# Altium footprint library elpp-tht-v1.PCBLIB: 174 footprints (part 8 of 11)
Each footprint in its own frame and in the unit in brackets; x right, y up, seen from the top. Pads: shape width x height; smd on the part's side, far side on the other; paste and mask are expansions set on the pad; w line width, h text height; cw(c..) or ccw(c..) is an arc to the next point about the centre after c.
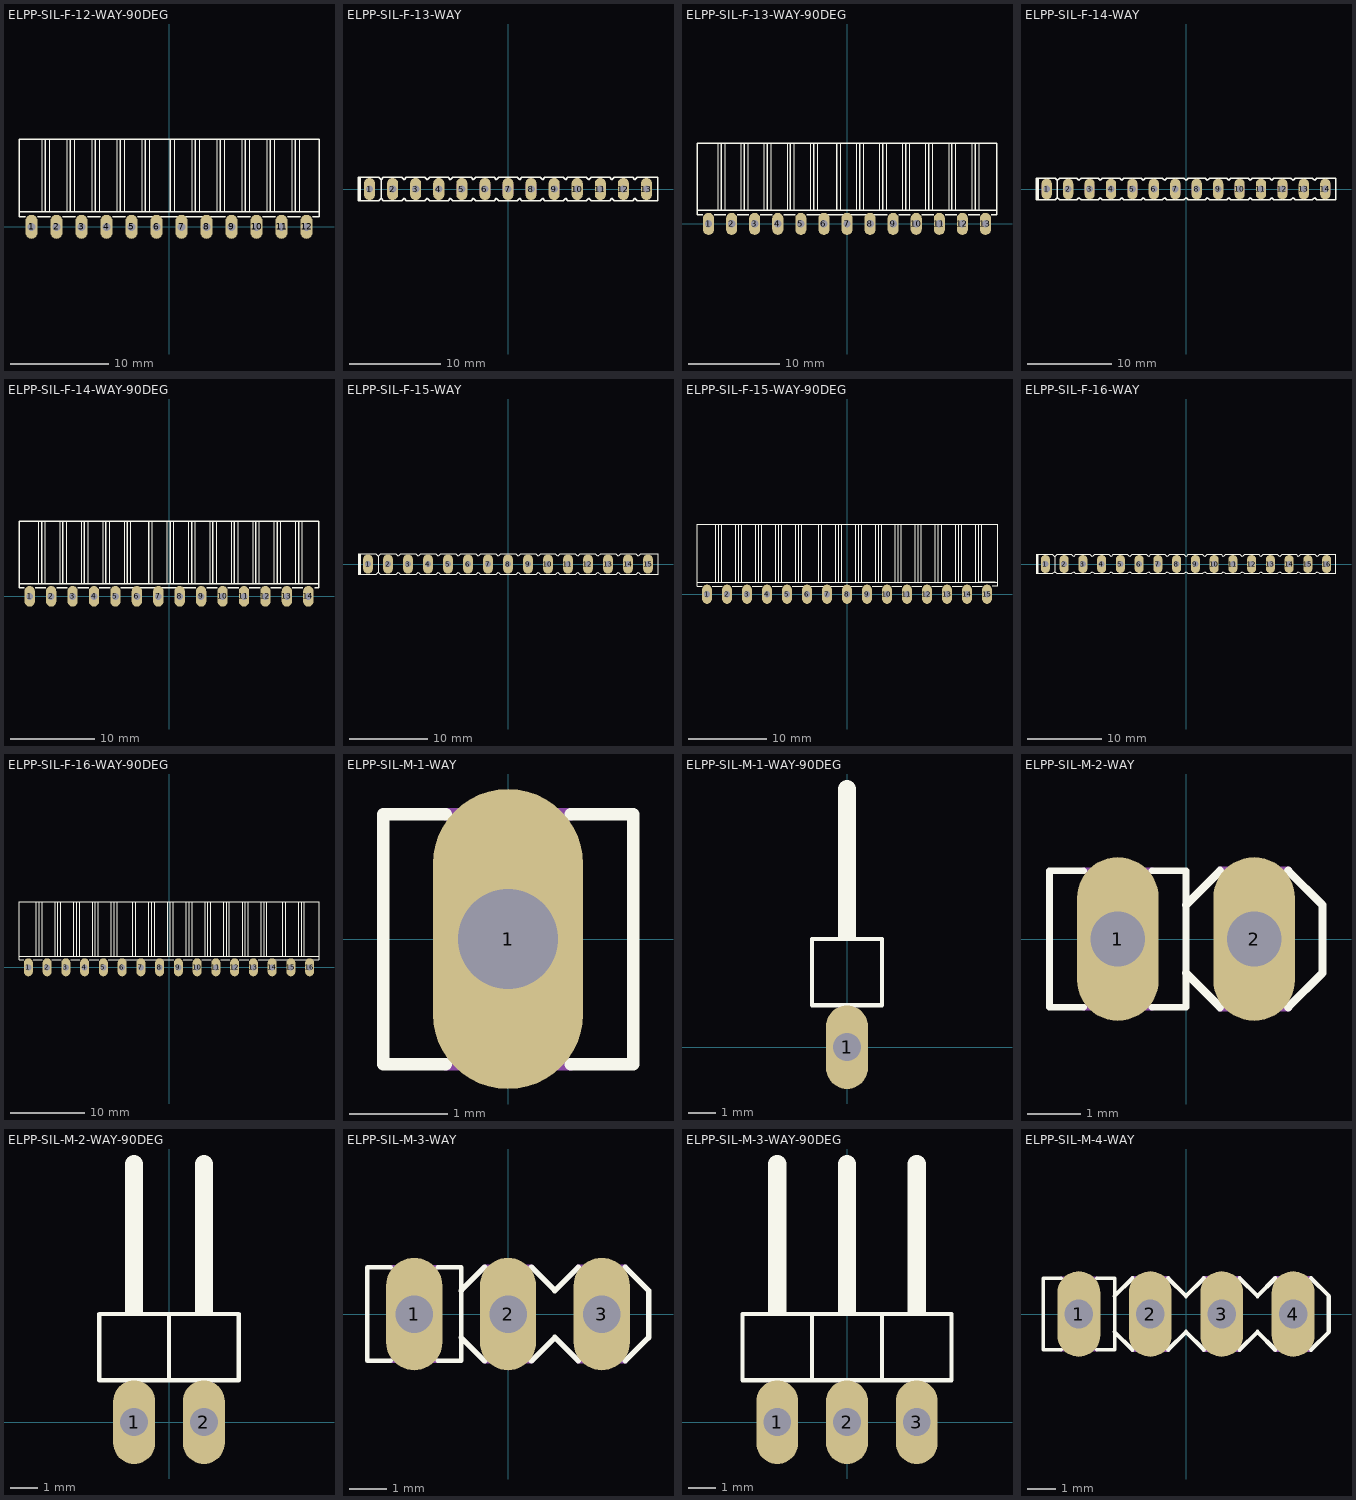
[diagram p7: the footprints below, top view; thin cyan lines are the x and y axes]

## ELPP-SIL-F-12-WAY-90DEG [mil]
pads (12):
  oval 48x96 hole 32: 1(-550,0) 2(-450,0) 3(-350,0) 4(-250,0) 5(-150,0) 6(-50,0) 7(50,0) 8(150,0) 9(250,0) 10(350,0) 11(450,0) 12(550,0)
Top Overlay:
  lines w2: -510,60 -510,350 ; -480,60 -480,350 ; -410,60 -410,350 ; -380,60 -380,350 ; -310,60 -310,350 ; -280,60 -280,350 ; -210,60 -210,350 ; -180,60 -180,350 ; -110,60 -110,350 ; -80,60 -80,350 ; 20,60 20,350 ; 90,60 90,350 ; 120,60 120,350 ; 190,60 190,350 ; 220,60 220,350 ; 290,60 290,350 ; 320,60 320,350 ; 390,60 390,350 ; 420,60 420,350 ; 490,60 490,350 ; 520,60 520,350
  lines w6: -575,40 -600,40 -600,60 ; -525,40 -475,40 ; -425,40 -375,40 ; -325,40 -275,40 ; -225,40 -175,40 ; -80,60 -95,60 ; -80,350 -95,350 ; -75,40 -125,40 200,40 225,40 ; -25,40 25,40 ; -10,60 5,60 ; 5,350 5,60 ; 75,40 125,40 ; 105,350 105,60 ; 120,60 105,60 ; 275,40 325,40 ; 375,40 425,40 ; 475,40 525,40 ; 575,40 600,40 600,60 ; -600,60 -600,350 -510,350 -495,350 ; -600,60 -510,60 -495,60 ; -495,60 -480,60 -410,60 -395,60 ; -495,60 -495,350 ; -495,350 -480,350 -410,350 -395,350 ; -395,60 -380,60 -310,60 -295,60 ; -395,60 -395,350 ; -395,350 -380,350 -310,350 -295,350 ; -295,60 -280,60 -210,60 -195,60 ; -295,60 -295,350 ; -295,350 -280,350 -210,350 -195,350 ; -195,60 -180,60 ; -195,60 -195,350 ; -195,350 -180,350 ; -180,60 190,60 200,60 205,60 ; -180,60 -110,60 -95,60 ; -180,350 190,350 200,350 205,350 ; -180,350 -110,350 -95,350 ; -95,60 -95,350 ; 5,60 20,60 90,60 105,60 ; 205,60 220,60 290,60 305,60 ; 205,60 205,350 ; 205,350 220,350 290,350 305,350 ; 305,60 320,60 390,60 405,60 ; 305,60 305,350 ; 305,350 320,350 390,350 405,350 ; 405,60 420,60 490,60 505,60 ; 405,60 405,350 ; 405,350 420,350 490,350 505,350 ; 505,60 520,60 ; 505,60 505,350 ; 505,350 520,350 ; 505,350 590,350 ; 505,350 520,350 ; 520,60 590,60 520,60 ; 520,60 600,60 ; 520,350 590,350 ; 520,350 600,350 600,60 ; 520,350 590,350
Mechanical 2:
  text ">NAME" at -620,40 h42.5
Mechanical 4:
  text ">VALUE" at 660,50 h42.5
Mechanical 16:
  rectangle: -560,0 -540,40
  rectangle: -460,0 -440,40
  rectangle: -360,0 -340,40
  rectangle: -260,0 -240,40
  rectangle: -160,0 -140,40
  rectangle: -60,0 -40,40
  rectangle: 40,0 60,40
  rectangle: 140,0 160,40
  rectangle: 240,0 260,40
  rectangle: 340,0 360,40
  rectangle: 440,0 460,40
  rectangle: 540,0 560,40
  text "2" at -420,100 h77.5
  text "5" at -115,100 h77.5
  text "3" at -320,100 h77.5
  text "4" at -220,100 h77.5
  text "1" at -520,100 h77.5
  text "6" at -15,100 h77.5
  text "7" at 85,100 h77.5
  text "8" at 185,100 h77.5
  text "10" at 380,100 h77.5
  text "11" at 480,100 h77.5
  text "12" at 580,100 h77.5
  text "9" at 280,100 h77.5

## ELPP-SIL-F-13-WAY [mil]
pads (13):
  oval 48x96 hole 32: 1(-600,0) 2(-500,0) 3(-400,0) 4(-300,0) 5(-200,0) 6(-100,0) 7(0,0) 8(100,0) 9(200,0) 10(300,0) 11(400,0) 12(500,0) 13(600,0)
Top Overlay:
  lines w6: -645,-50 -650,-50 -650,50 -645,50 ; -645,-50 -640,-50 ; -645,-50 -645,50 ; -645,50 -640,50 ; -640,-50 -560,-50 -550,-40 ; -640,-50 -640,50 ; -640,50 -560,50 -550,40 ; -550,-40 -540,-50 -460,-50 -450,-40 -440,-50 -360,-50 -350,-40 -340,-50 -260,-50 -250,-40 -240,-50 -160,-50 -150,-40 -140,-50 -60,-50 -50,-40 -40,-50 40,-50 50,-40 60,-50 140,-50 150,-40 160,-50 240,-50 250,-40 260,-50 340,-50 350,-40 360,-50 440,-50 450,-40 460,-50 540,-50 550,-40 560,-50 650,-50 650,50 560,50 550,40 540,50 460,50 450,40 440,50 360,50 350,40 340,50 260,50 250,40 240,50 160,50 150,40 140,50 60,50 50,40 40,50 -40,50 -50,40 -60,50 -140,50 -150,40 -160,50 -240,50 -250,40 -260,50 -340,50 -350,40 -360,50 -440,50 -450,40 -460,50 -540,50 -550,40 ; -550,-40 -550,40
Mechanical 2:
  text ">NAME" at -650,65 h42.5
Mechanical 4:
  text ">VALUE" at 350,65 h42.5
Mechanical 16:
  drawing of 182 lines, arcs and shapes, not listed

## ELPP-SIL-F-13-WAY-90DEG [mil]
pads (13):
  oval 48x96 hole 32: 1(-600,0) 2(-500,0) 3(-400,0) 4(-300,0) 5(-200,0) 6(-100,0) 7(0,0) 8(100,0) 9(200,0) 10(300,0) 11(400,0) 12(500,0) 13(600,0)
Top Overlay:
  lines w2: -560,60 -560,350 ; -530,60 -530,350 ; -460,60 -460,350 ; -430,60 -430,350 ; -360,60 -360,350 ; -330,60 -330,350 ; -260,60 -260,350 ; -230,60 -230,350 ; -160,60 -160,350 ; -130,60 -130,350 ; -30,60 -30,350 ; 40,60 40,350 ; 70,60 70,350 ; 140,60 140,350 ; 170,60 170,350 ; 240,60 240,350 ; 270,60 270,350 ; 340,60 340,350 ; 370,60 370,350 ; 440,60 440,350 ; 470,60 470,350 ; 540,60 540,350 ; 570,60 570,350
  lines w6: -625,40 -650,40 -650,60 ; -575,40 -525,40 ; -475,40 -425,40 ; -375,40 -325,40 ; -275,40 -225,40 ; -130,60 -145,60 ; -130,350 -145,350 ; -125,40 -175,40 150,40 175,40 ; -75,40 -25,40 ; -60,60 -45,60 ; -45,350 -45,60 ; 25,40 75,40 ; 55,350 55,60 ; 70,60 55,60 ; 225,40 275,40 ; 325,40 375,40 ; 425,40 475,40 ; 525,40 575,40 ; 625,40 650,40 650,60 ; 640,60 570,60 ; 640,350 570,350 ; -650,60 -650,350 -560,350 -545,350 ; -650,60 -560,60 -545,60 ; -545,60 -530,60 -460,60 -445,60 ; -545,60 -545,350 ; -545,350 -530,350 -460,350 -445,350 ; -445,60 -430,60 -360,60 -345,60 ; -445,60 -445,350 ; -445,350 -430,350 -360,350 -345,350 ; -345,60 -330,60 -260,60 -245,60 ; -345,60 -345,350 ; -345,350 -330,350 -260,350 -245,350 ; -245,60 -230,60 ; -245,60 -245,350 ; -245,350 -230,350 ; -230,60 140,60 150,60 155,60 ; -230,60 -160,60 -145,60 ; -230,350 140,350 150,350 155,350 ; -230,350 -160,350 -145,350 ; -145,60 -145,350 ; -45,60 -30,60 40,60 55,60 ; 155,60 170,60 240,60 255,60 ; 155,60 155,350 ; 155,350 170,350 240,350 255,350 ; 255,60 270,60 340,60 355,60 ; 255,60 255,350 ; 255,350 270,350 340,350 355,350 ; 355,60 370,60 440,60 455,60 ; 355,60 355,350 ; 355,350 370,350 440,350 455,350 ; 455,60 470,60 540,60 555,60 ; 455,60 455,350 ; 455,350 470,350 540,350 555,350 ; 555,60 570,60 ; 555,60 555,350 ; 555,350 570,350 ; 570,60 650,60 ; 570,350 650,350 650,60
Mechanical 2:
  text ">NAME" at -670,40 h42.5
Mechanical 4:
  text ">VALUE" at 710,50 h42.5
Mechanical 16:
  rectangle: -610,0 -590,40
  rectangle: -510,0 -490,40
  rectangle: -410,0 -390,40
  rectangle: -310,0 -290,40
  rectangle: -210,0 -190,40
  rectangle: -110,0 -90,40
  rectangle: -10,0 10,40
  rectangle: 90,0 110,40
  rectangle: 190,0 210,40
  rectangle: 290,0 310,40
  rectangle: 390,0 410,40
  rectangle: 490,0 510,40
  rectangle: 590,0 610,40
  text "2" at -470,100 h77.5
  text "5" at -165,100 h77.5
  text "3" at -370,100 h77.5
  text "4" at -270,100 h77.5
  text "1" at -570,100 h77.5
  text "6" at -65,100 h77.5
  text "7" at 35,100 h77.5
  text "8" at 135,100 h77.5
  text "10" at 330,100 h77.5
  text "13" at 635,100 h77.5
  text "11" at 430,100 h77.5
  text "12" at 530,100 h77.5
  text "9" at 230,100 h77.5

## ELPP-SIL-F-14-WAY [mil]
pads (14):
  oval 48x96 hole 32: 1(-650,0) 2(-550,0) 3(-450,0) 4(-350,0) 5(-250,0) 6(-150,0) 7(-50,0) 8(50,0) 9(150,0) 10(250,0) 11(350,0) 12(450,0) 13(550,0) 14(650,0)
Top Overlay:
  lines w6: -695,-50 -700,-50 -700,50 -695,50 ; -695,-50 -690,-50 ; -695,-50 -695,50 ; -695,50 -690,50 ; -690,-50 -610,-50 -600,-40 ; -690,-50 -690,50 ; -690,50 -610,50 -600,40 ; -600,-40 -590,-50 -510,-50 -500,-40 -490,-50 -410,-50 -400,-40 -390,-50 -310,-50 -300,-40 -290,-50 -210,-50 -200,-40 -190,-50 -110,-50 -100,-40 -90,-50 -10,-50 0,-40 10,-50 90,-50 100,-40 110,-50 190,-50 200,-40 210,-50 290,-50 300,-40 310,-50 390,-50 400,-40 410,-50 490,-50 500,-40 510,-50 590,-50 600,-40 610,-50 700,-50 700,50 610,50 600,40 590,50 510,50 500,40 490,50 410,50 400,40 390,50 310,50 300,40 290,50 210,50 200,40 190,50 110,50 100,40 90,50 10,50 0,40 -10,50 -90,50 -100,40 -110,50 -190,50 -200,40 -210,50 -290,50 -300,40 -310,50 -390,50 -400,40 -410,50 -490,50 -500,40 -510,50 -590,50 -600,40 ; -600,-40 -600,40
Mechanical 2:
  text ">NAME" at -700,65 h42.5
Mechanical 4:
  text ">VALUE" at 400,65 h42.5
Mechanical 16:
  drawing of 196 lines, arcs and shapes, not listed

## ELPP-SIL-F-14-WAY-90DEG [mil]
pads (14):
  oval 48x96 hole 32: 1(-650,0) 2(-550,0) 3(-450,0) 4(-350,0) 5(-250,0) 6(-150,0) 7(-50,0) 8(50,0) 9(150,0) 10(250,0) 11(350,0) 12(450,0) 13(550,0) 14(650,0)
Top Overlay:
  lines w2: -610,60 -610,350 ; -580,60 -580,350 ; -510,60 -510,350 ; -480,60 -480,350 ; -410,60 -410,350 ; -380,60 -380,350 ; -310,60 -310,350 ; -280,60 -280,350 ; -210,60 -210,350 ; -180,60 -180,350 ; -80,60 -80,350 ; -10,60 -10,350 ; 20,60 20,350 ; 90,60 90,350 ; 120,60 120,350 ; 190,60 190,350 ; 220,60 220,350 ; 290,60 290,350 ; 320,60 320,350 ; 390,60 390,350 ; 420,60 420,350 ; 490,60 490,350 ; 520,60 520,350 ; 590,60 590,350 ; 620,60 620,350
  lines w6: -675,40 -700,40 -700,60 ; -625,40 -575,40 ; -525,40 -475,40 ; -425,40 -375,40 ; -325,40 -275,40 ; -180,60 -195,60 ; -180,350 -195,350 ; -175,40 -225,40 100,40 125,40 ; -125,40 -75,40 ; -110,60 -95,60 ; -95,350 -95,60 ; -25,40 25,40 ; 5,350 5,60 ; 20,60 5,60 ; 175,40 225,40 ; 275,40 325,40 ; 375,40 425,40 ; 475,40 525,40 ; 575,40 625,40 ; 620,60 605,60 ; 620,350 605,350 ; 680,40 700,40 700,60 ; -700,60 -700,350 -610,350 -595,350 ; -700,60 -610,60 -595,60 ; -595,60 -580,60 -510,60 -495,60 ; -595,60 -595,350 ; -595,350 -580,350 -510,350 -495,350 ; -495,60 -480,60 -410,60 -395,60 ; -495,60 -495,350 ; -495,350 -480,350 -410,350 -395,350 ; -395,60 -380,60 -310,60 -295,60 ; -395,60 -395,350 ; -395,350 -380,350 -310,350 -295,350 ; -295,60 -280,60 ; -295,60 -295,350 ; -295,350 -280,350 ; -280,60 90,60 100,60 105,60 ; -280,60 -210,60 -195,60 ; -280,350 90,350 100,350 105,350 ; -280,350 -210,350 -195,350 ; -195,60 -195,350 ; -95,60 -80,60 -10,60 5,60 ; 105,60 120,60 190,60 205,60 ; 105,60 105,350 ; 105,350 120,350 190,350 205,350 ; 205,60 220,60 290,60 305,60 ; 205,60 205,350 ; 205,350 220,350 290,350 305,350 ; 305,60 320,60 390,60 405,60 ; 305,60 305,350 ; 305,350 320,350 390,350 405,350 ; 405,60 420,60 490,60 505,60 ; 405,60 405,350 ; 405,350 420,350 490,350 505,350 ; 505,60 520,60 ; 505,60 505,350 ; 505,350 520,350 ; 520,60 700,60 ; 520,60 590,60 605,60 ; 520,350 700,350 700,60 ; 520,350 590,350 605,350 ; 605,60 605,350
Mechanical 2:
  text ">NAME" at -720,40 h42.5
Mechanical 4:
  text ">VALUE" at 760,50 h42.5
Mechanical 16:
  rectangle: -660,0 -640,40
  rectangle: -560,0 -540,40
  rectangle: -460,0 -440,40
  rectangle: -360,0 -340,40
  rectangle: -260,0 -240,40
  rectangle: -160,0 -140,40
  rectangle: -60,0 -40,40
  rectangle: 40,0 60,40
  rectangle: 140,0 160,40
  rectangle: 240,0 260,40
  rectangle: 340,0 360,40
  rectangle: 440,0 460,40
  rectangle: 540,0 560,40
  rectangle: 640,0 660,40
  text "2" at -520,100 h77.5
  text "5" at -215,100 h77.5
  text "3" at -420,100 h77.5
  text "4" at -320,100 h77.5
  text "1" at -620,100 h77.5
  text "6" at -115,100 h77.5
  text "7" at -15,100 h77.5
  text "8" at 85,100 h77.5
  text "10" at 280,100 h77.5
  text "13" at 585,100 h77.5
  text "11" at 380,100 h77.5
  text "12" at 480,100 h77.5
  text "9" at 180,100 h77.5
  text "14" at 685,100 h77.5

## ELPP-SIL-F-15-WAY [mil]
pads (15):
  oval 48x96 hole 32: 1(-700,0) 2(-600,0) 3(-500,0) 4(-400,0) 5(-300,0) 6(-200,0) 7(-100,0) 8(0,0) 9(100,0) 10(200,0) 11(300,0) 12(400,0) 13(500,0) 14(600,0) 15(700,0)
Top Overlay:
  lines w6: -745,-50 -750,-50 -750,50 -745,50 ; -745,-50 -740,-50 ; -745,-50 -745,50 ; -745,50 -740,50 ; -740,-50 -660,-50 -650,-40 ; -740,-50 -740,50 ; -740,50 -660,50 -650,40 ; -650,-40 -640,-50 -560,-50 -550,-40 -540,-50 -460,-50 -450,-40 -440,-50 -360,-50 -350,-40 -340,-50 -260,-50 -250,-40 -240,-50 -160,-50 -150,-40 -140,-50 -60,-50 -50,-40 -40,-50 40,-50 50,-40 60,-50 140,-50 150,-40 160,-50 240,-50 250,-40 260,-50 340,-50 350,-40 360,-50 440,-50 450,-40 460,-50 540,-50 550,-40 560,-50 640,-50 650,-40 660,-50 750,-50 750,50 660,50 650,40 640,50 560,50 550,40 540,50 460,50 450,40 440,50 360,50 350,40 340,50 260,50 250,40 240,50 160,50 150,40 140,50 60,50 50,40 40,50 -40,50 -50,40 -60,50 -140,50 -150,40 -160,50 -240,50 -250,40 -260,50 -340,50 -350,40 -360,50 -440,50 -450,40 -460,50 -540,50 -550,40 -560,50 -640,50 -650,40 ; -650,-40 -650,40
Mechanical 2:
  text ">NAME" at -750,65 h42.5
Mechanical 4:
  text ">VALUE" at 450,65 h42.5
Mechanical 16:
  drawing of 210 lines, arcs and shapes, not listed

## ELPP-SIL-F-15-WAY-90DEG [mil]
pads (15):
  oval 48x96 hole 32: 1(-700,0) 2(-600,0) 3(-500,0) 4(-400,0) 5(-300,0) 6(-200,0) 7(-100,0) 8(0,0) 9(100,0) 10(200,0) 11(300,0) 12(400,0) 13(500,0) 14(600,0) 15(700,0)
Top Overlay:
  lines w2: -660,60 -660,350 ; -630,60 -630,350 ; -560,60 -560,350 ; -530,60 -530,350 ; -460,60 -460,350 ; -430,60 -430,350 ; -360,60 -360,350 ; -330,60 -330,350 ; -260,60 -260,350 ; -230,60 -230,350 ; -130,60 -130,350 ; -60,60 -60,350 ; -30,60 -30,350 ; 40,60 40,350 ; 70,60 70,350 ; 140,60 140,350 ; 170,60 170,350 ; 240,60 240,350 ; 270,60 270,350 ; 340,60 340,350 ; 370,60 370,350 ; 440,60 440,350 ; 470,60 470,350 ; 540,60 540,350 ; 570,60 570,350 ; 640,60 640,350 ; 670,60 670,350
  lines w6: -725,40 -750,40 -750,60 ; -675,40 -625,40 ; -575,40 -525,40 ; -475,40 -425,40 ; -375,40 -325,40 ; -230,60 -245,60 ; -230,350 -245,350 ; -225,40 -275,40 50,40 75,40 ; -175,40 -125,40 ; -160,60 -145,60 ; -145,350 -145,60 ; -75,40 -25,40 ; -45,350 -45,60 ; -30,60 -45,60 ; 125,40 175,40 ; 225,40 275,40 ; 325,40 375,40 ; 425,40 475,40 ; 525,40 575,40 ; 570,60 555,60 ; 570,350 555,350 ; 625,40 675,40 ; 655,350 655,60 ; 725,40 750,40 750,60 ; -750,60 -750,350 -660,350 -645,350 ; -750,60 -660,60 -645,60 ; -645,60 -630,60 -560,60 -545,60 ; -645,60 -645,350 ; -645,350 -630,350 -560,350 -545,350 ; -545,60 -530,60 -460,60 -445,60 ; -545,60 -545,350 ; -545,350 -530,350 -460,350 -445,350 ; -445,60 -430,60 -360,60 -345,60 ; -445,60 -445,350 ; -445,350 -430,350 -360,350 -345,350 ; -345,60 -330,60 ; -345,60 -345,350 ; -345,350 -330,350 ; -330,60 40,60 50,60 55,60 ; -330,60 -260,60 -245,60 ; -330,350 40,350 50,350 55,350 ; -330,350 -260,350 -245,350 ; -245,60 -245,350 ; -145,60 -130,60 -60,60 -45,60 ; 55,60 70,60 140,60 155,60 ; 55,60 55,350 ; 55,350 70,350 140,350 155,350 ; 155,60 170,60 240,60 255,60 ; 155,60 155,350 ; 155,350 170,350 240,350 255,350 ; 255,60 270,60 340,60 355,60 ; 255,60 255,350 ; 255,350 270,350 340,350 355,350 ; 355,60 370,60 440,60 455,60 ; 355,60 355,350 ; 355,350 370,350 440,350 455,350 ; 455,60 470,60 ; 455,60 455,350 ; 455,350 470,350 ; 470,60 640,60 ; 470,60 540,60 555,60 ; 470,350 640,350 750,350 750,60 ; 470,350 540,350 555,350 ; 555,60 555,350 ; 640,60 750,60 ; 640,60 655,60 ; 655,60 670,60 ; 655,60 740,60 670,60 ; 655,60 670,60
Mechanical 2:
  text ">NAME" at -770,40 h42.5
Mechanical 4:
  text ">VALUE" at 810,50 h42.5
Mechanical 16:
  rectangle: -710,0 -690,40
  rectangle: -610,0 -590,40
  rectangle: -510,0 -490,40
  rectangle: -410,0 -390,40
  rectangle: -310,0 -290,40
  rectangle: -210,0 -190,40
  rectangle: -110,0 -90,40
  rectangle: -10,0 10,40
  rectangle: 90,0 110,40
  rectangle: 190,0 210,40
  rectangle: 290,0 310,40
  rectangle: 390,0 410,40
  rectangle: 490,0 510,40
  rectangle: 590,0 610,40
  rectangle: 690,0 710,40
  text "2" at -570,100 h77.5
  text "5" at -265,100 h77.5
  text "3" at -470,100 h77.5
  text "4" at -370,100 h77.5
  text "1" at -670,100 h77.5
  text "6" at -165,100 h77.5
  text "7" at -65,100 h77.5
  text "8" at 35,100 h77.5
  text "10" at 230,100 h77.5
  text "13" at 535,100 h77.5
  text "11" at 330,100 h77.5
  text "12" at 430,100 h77.5
  text "9" at 130,100 h77.5
  text "14" at 635,100 h77.5
  text "15" at 735,100 h77.5

## ELPP-SIL-F-16-WAY [mil]
pads (16):
  oval 48x96 hole 32: 1(-750,0) 2(-650,0) 3(-550,0) 4(-450,0) 5(-350,0) 6(-250,0) 7(-150,0) 8(-50,0) 9(50,0) 10(150,0) 11(250,0) 12(350,0) 13(450,0) 14(550,0) 15(650,0) 16(750,0)
Top Overlay:
  lines w6: -795,-50 -800,-50 -800,50 -795,50 ; -795,-50 -790,-50 ; -795,-50 -795,50 ; -795,50 -790,50 ; -790,-50 -710,-50 -700,-40 ; -790,-50 -790,50 ; -790,50 -710,50 -700,40 ; -700,-40 -690,-50 -610,-50 -600,-40 -590,-50 -510,-50 -500,-40 -490,-50 -410,-50 -400,-40 -390,-50 -310,-50 -300,-40 -290,-50 -210,-50 -200,-40 -190,-50 -110,-50 -100,-40 -90,-50 -10,-50 0,-40 10,-50 90,-50 100,-40 110,-50 190,-50 200,-40 210,-50 290,-50 300,-40 310,-50 390,-50 400,-40 410,-50 490,-50 500,-40 510,-50 590,-50 600,-40 610,-50 690,-50 700,-40 710,-50 800,-50 800,50 710,50 700,40 690,50 610,50 600,40 590,50 510,50 500,40 490,50 410,50 400,40 390,50 310,50 300,40 290,50 210,50 200,40 190,50 110,50 100,40 90,50 10,50 0,40 -10,50 -90,50 -100,40 -110,50 -190,50 -200,40 -210,50 -290,50 -300,40 -310,50 -390,50 -400,40 -410,50 -490,50 -500,40 -510,50 -590,50 -600,40 -610,50 -690,50 -700,40 ; -700,-40 -700,40
Mechanical 2:
  text ">NAME" at -800,65 h42.5
Mechanical 4:
  text ">VALUE" at 500,65 h42.5
Mechanical 16:
  drawing of 224 lines, arcs and shapes, not listed

## ELPP-SIL-F-16-WAY-90DEG [mil]
pads (16):
  oval 48x96 hole 32: 1(-750,0) 2(-650,0) 3(-550,0) 4(-450,0) 5(-350,0) 6(-250,0) 7(-150,0) 8(-50,0) 9(50,0) 10(150,0) 11(250,0) 12(350,0) 13(450,0) 14(550,0) 15(650,0) 16(750,0)
Top Overlay:
  lines w2: -710,60 -710,350 ; -680,60 -680,350 ; -610,60 -610,350 ; -580,60 -580,350 ; -510,60 -510,350 ; -480,60 -480,350 ; -410,60 -410,350 ; -380,60 -380,350 ; -310,60 -310,350 ; -280,60 -280,350 ; -180,60 -180,350 ; -110,60 -110,350 ; -80,60 -80,350 ; -10,60 -10,350 ; 20,60 20,350 ; 90,60 90,350 ; 120,60 120,350 ; 190,60 190,350 ; 220,60 220,350 ; 290,60 290,350 ; 320,60 320,350 ; 390,60 390,350 ; 420,60 420,350 ; 490,60 490,350 ; 520,60 520,350 ; 620,60 620,350 ; 690,60 690,350 ; 720,60 720,350
  lines w6: -775,40 -800,40 -800,60 ; -725,40 -675,40 ; -625,40 -575,40 ; -525,40 -475,40 ; -425,40 -375,40 ; -280,60 -295,60 ; -280,350 -295,350 ; -275,40 -325,40 0,40 25,40 ; -225,40 -175,40 ; -210,60 -195,60 ; -195,350 -195,60 ; -125,40 -75,40 ; -95,350 -95,60 ; -80,60 -95,60 ; 75,40 125,40 ; 175,40 225,40 ; 275,40 325,40 ; 375,40 425,40 ; 520,60 505,60 ; 520,350 505,350 ; 525,40 475,40 800,40 800,60 ; 575,40 625,40 ; 590,60 605,60 ; 605,350 605,60 ; 675,40 725,40 ; 705,350 705,60 ; 720,60 705,60 ; -800,60 -800,350 -710,350 -695,350 ; -800,60 -710,60 -695,60 ; -695,60 -680,60 -610,60 -595,60 ; -695,60 -695,350 ; -695,350 -680,350 -610,350 -595,350 ; -595,60 -580,60 -510,60 -495,60 ; -595,60 -595,350 ; -595,350 -580,350 -510,350 -495,350 ; -495,60 -480,60 -410,60 -395,60 ; -495,60 -495,350 ; -495,350 -480,350 -410,350 -395,350 ; -395,60 -380,60 ; -395,60 -395,350 ; -395,350 -380,350 ; -380,60 -10,60 0,60 5,60 ; -380,60 -310,60 -295,60 ; -380,350 -10,350 0,350 5,350 ; -380,350 -310,350 -295,350 ; -295,60 -295,350 ; -195,60 -180,60 -110,60 -95,60 ; 5,60 20,60 90,60 105,60 ; 5,60 5,350 ; 5,350 20,350 90,350 105,350 ; 105,60 120,60 190,60 205,60 ; 105,60 105,350 ; 105,350 120,350 190,350 205,350 ; 205,60 220,60 290,60 305,60 ; 205,60 205,350 ; 205,350 220,350 290,350 305,350 ; 305,60 320,60 390,60 405,60 ; 305,60 305,350 ; 305,350 320,350 390,350 405,350 ; 405,60 420,60 ; 405,60 405,350 ; 405,350 420,350 ; 420,60 800,60 ; 420,60 490,60 505,60 ; 420,350 800,350 800,60 ; 420,350 490,350 505,350 ; 505,60 505,350 ; 605,60 620,60 690,60 705,60
Mechanical 2:
  text ">NAME" at -820,40 h42.5
Mechanical 4:
  text ">VALUE" at 860,50 h42.5
Mechanical 16:
  rectangle: -760,0 -740,40
  rectangle: -660,0 -640,40
  rectangle: -560,0 -540,40
  rectangle: -460,0 -440,40
  rectangle: -360,0 -340,40
  rectangle: -260,0 -240,40
  rectangle: -160,0 -140,40
  rectangle: -60,0 -40,40
  rectangle: 40,0 60,40
  rectangle: 140,0 160,40
  rectangle: 240,0 260,40
  rectangle: 340,0 360,40
  rectangle: 440,0 460,40
  rectangle: 540,0 560,40
  rectangle: 640,0 660,40
  rectangle: 740,0 760,40
  text "2" at -620,100 h77.5
  text "5" at -315,100 h77.5
  text "3" at -520,100 h77.5
  text "4" at -420,100 h77.5
  text "1" at -720,100 h77.5
  text "6" at -215,100 h77.5
  text "7" at -115,100 h77.5
  text "8" at -15,100 h77.5
  text "10" at 180,100 h77.5
  text "13" at 485,100 h77.5
  text "11" at 280,100 h77.5
  text "12" at 380,100 h77.5
  text "9" at 80,100 h77.5
  text "14" at 585,100 h77.5
  text "15" at 685,100 h77.5
  text "16" at 785,100 h77.5

## ELPP-SIL-M-1-WAY [mil]
pads (1):
  oval 60x120 hole 40: 1(0,0)
Top Overlay:
  lines w5: -25,-50 -50,-50 -50,50 -25,50 ; 25,-50 50,-50 50,50 25,50
Mechanical 2:
  text ">NAME" at -50,75 h42.5
Mechanical 4:
  text ">VALUE" at -50,-125 h42.5
Mechanical 16:
  rectangle: -10,-10 10,10
  lines w5: -25,-50 25,-50 ; -25,50 25,50

## ELPP-SIL-M-1-WAY-90DEG [mil]
pads (1):
  oval 60x120 hole 40: 1(0,0)
Top Overlay:
  rectangle: -13,155 13,185
  lines w6: -50,60 50,60 50,155 -50,155 -50,60
  lines w26: 0,185 0,370
Mechanical 2:
  text ">NAME" at -60,140 h42.5
Mechanical 4:
  text ">VALUE" at 70,95 h42.5
Mechanical 16:
  rectangle: -13,34 13,60
  rectangle: -13,-13 13,34

## ELPP-SIL-M-2-WAY [mil]
pads (2):
  oval 60x120 hole 40: 1(-50,0) 2(50,0)
Top Overlay:
  lines w5: -75,-50 -100,-50 -100,50 -75,50 ; -25,-50 0,-50 0,50 -25,50
  lines w6: 0,-25 25,-50 ; 0,25 25,50 ; 75,-50 100,-25 100,25 75,50
Mechanical 2:
  text ">NAME" at -100,75 h42.5
Mechanical 4:
  text ">VALUE" at -100,-125 h42.5
Mechanical 16:
  rectangle: 40,-10 60,10
  rectangle: -60,-10 -40,10
  lines w5: -75,-50 -25,-50 ; -75,50 -25,50
  lines w6: 25,-50 75,-50 ; 25,50 75,50

## ELPP-SIL-M-2-WAY-90DEG [mil]
pads (2):
  oval 60x120 hole 40: 1(-50,0) 2(50,0)
Top Overlay:
  rectangle: -63,155 -37,185
  rectangle: 37,155 63,185
  lines w6: 0,60 0,155 ; 0,60 -100,60 -100,155 0,155 ; 0,60 100,60 100,155 0,155
  lines w26: -50,185 -50,370 ; 50,185 50,370
Mechanical 2:
  text ">NAME" at -110,140 h42.5
Mechanical 4:
  text ">VALUE" at 120,95 h42.5
Mechanical 16:
  rectangle: 37,34 63,60
  rectangle: -63,34 -37,60
  rectangle: 37,-13 63,34
  rectangle: -63,-13 -37,34
  text "1" at -25,95 h77.5
  text "2" at 75,95 h77.5

## ELPP-SIL-M-3-WAY [mil]
pads (3):
  oval 60x120 hole 40: 1(-100,0) 2(0,0) 3(100,0)
Top Overlay:
  lines w5: -125,-50 -150,-50 -150,50 -125,50 ; -75,-50 -50,-50 -50,50 -75,50
  lines w6: -50,-25 -25,-50 ; -50,25 -25,50 ; 25,-50 50,-25 75,-50 ; 25,50 50,25 75,50 ; 125,-50 150,-25 150,25 125,50
Mechanical 2:
  text ">NAME" at -150,75 h42.5
Mechanical 4:
  text ">VALUE" at -150,-125 h42.5
Mechanical 16:
  rectangle: -10,-10 10,10
  rectangle: -110,-10 -90,10
  rectangle: 90,-10 110,10
  lines w5: -125,-50 -75,-50 ; -125,50 -75,50
  lines w6: -25,-50 25,-50 ; -25,50 25,50 ; 75,-50 125,-50 ; 75,50 125,50

## ELPP-SIL-M-3-WAY-90DEG [mil]
pads (3):
  oval 60x120 hole 40: 1(-100,0) 2(0,0) 3(100,0)
Top Overlay:
  rectangle: -113,155 -87,185
  rectangle: -13,155 13,185
  rectangle: 87,155 113,185
  lines w6: -50,60 -50,155 ; -50,60 -150,60 -150,155 -50,155 ; -50,60 50,60 ; -50,155 50,155 ; 50,60 150,60 150,155 50,155 ; 50,60 50,155
  lines w26: -100,185 -100,370 ; 0,185 0,370 ; 100,185 100,370
Mechanical 2:
  text ">NAME" at -160,140 h42.5
Mechanical 4:
  text ">VALUE" at 170,95 h42.5
Mechanical 16:
  rectangle: 87,34 113,60
  rectangle: 87,-13 113,34
  rectangle: -13,34 13,60
  rectangle: -113,34 -87,60
  rectangle: -13,-13 13,34
  rectangle: -113,-13 -87,34
  text "1" at -75,95 h77.5
  text "2" at 25,95 h77.5
  text "3" at 125,95 h77.5

## ELPP-SIL-M-4-WAY [mil]
pads (4):
  oval 60x120 hole 40: 1(-150,0) 2(-50,0) 3(50,0) 4(150,0)
Top Overlay:
  lines w5: -175,-50 -200,-50 -200,50 -175,50 ; -125,-50 -100,-50 -100,50 -125,50
  lines w6: -100,-25 -75,-50 ; -100,25 -75,50 ; -25,-50 0,-25 25,-50 ; -25,50 0,25 25,50 ; 75,-50 100,-25 125,-50 ; 75,50 100,25 125,50 ; 175,-50 200,-25 200,25 175,50
Mechanical 2:
  text ">NAME" at -200,75 h42.5
Mechanical 4:
  text ">VALUE" at -200,-125 h42.5
Mechanical 16:
  rectangle: -60,-10 -40,10
  rectangle: -160,-10 -140,10
  rectangle: 40,-10 60,10
  rectangle: 140,-10 160,10
  lines w5: -175,-50 -125,-50 ; -175,50 -125,50
  lines w6: -75,-50 -25,-50 ; -75,50 -25,50 ; 25,-50 75,-50 ; 25,50 75,50 ; 125,-50 175,-50 ; 125,50 175,50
